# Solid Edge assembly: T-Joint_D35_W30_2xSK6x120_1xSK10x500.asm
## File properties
Author: fknapp
Template: iso metric assembly.asm
Last saved by: fknapp
Revision: 21
Application: Solid Edge
Username: fknapp
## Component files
T-Joint_D35_W30.par
SK Schraube 10x500_ohne_Gewinde_22042020.par
SK Schraube 6x120_ohne_Gewinde.par
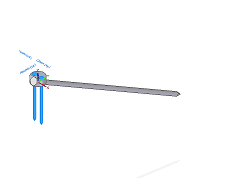
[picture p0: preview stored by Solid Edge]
